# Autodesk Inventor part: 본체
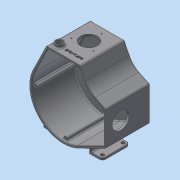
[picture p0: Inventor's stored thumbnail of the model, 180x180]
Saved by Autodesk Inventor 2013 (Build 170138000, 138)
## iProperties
Created: 2017-05
Part Number: 본체
Material: 알루미늄 6061
Document SubType Name: Modeling
Designer: mduedu
Density: 2.71 g/cm^3
Mass: 1300.76 g
Surface Area: 1825.93 cm^2
Volume: 479.984 cm^3
Author: mduedu
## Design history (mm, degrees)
sketch "스케치1"
  geometry: L1 (-71.801, 35.28)-(-40, 100); L2 (-40, 100)-(40, 100); L3 (40, 100)-(59.768, 59.768); L4 (59.768, 59.768)-(100, 40); L5 (100, 40)-(100, -40); L6 (100, -40)-(35.28, -71.801); A1 r 80 centre (0, 0) between (-71.801, 35.28) and (35.28, -71.801); 3 further points
  constraints: 12 end point, 4 tangent, 2 midpoint, 2 point on circle, 1 centre point, 1 coincident, 1 horizontal, 1 horizontal alignment, 1 perpendicular, 1 vertical alignment
  dimensions: "d0" = 160 diameter of A1; "d2" = 100 distance from line of L2 point (0, 0); "d3" = 100 distance from line of L5 point (0, 0); "d4" = 80 distance of L1.end L2.end; "d5" = 80 distance of L4.end L5.end
extrude "돌출1" new body sketch "스케치1" distance "d6" = 5; taper "d7" = 0 deg
fillet "모깎기1" dims "d8" = 50
sketch "스케치2"
  geometry: C1 r 22 at (0, 0); 1 further point
  constraints: 1 centre point, 1 coincident
  dimensions: "d9" = 44 diameter of C1
extrude "돌출2" join sketch "스케치2" distance "d10" = 22.5; taper "d11" = 0 deg
sketch "스케치3"
  geometry: C1 r 18.5 at (0, 0); 1 further point
  constraints: 1 centre point, 1 coincident
  dimensions: "d12" = 37 diameter of C1
extrude "돌출3" cut sketch "스케치3" distance "d13" = 9; taper "d14" = 0 deg
fillet "모깎기2" dims "d15" = 3
sketch "스케치4"
  geometry: L1 (35.28, -71.801)-(100, -40) reference; L2 (100, -40)-(100, 40) reference; L3 (100, 40)-(75.073, 52.248) reference; L4 (52.248, 75.073)-(40, 100) reference; L5 (40, 100)-(-40, 100) reference; L6 (-40, 100)-(-71.801, 35.28) reference; L7 (-36.886, 95)-(36.886, 95); L8 (36.886, 95)-(47.76, 72.868); L9 (72.868, 47.76)-(95, 36.886); L10 (95, 36.886)-(95, -36.886); L11 (95, -36.886)-(33.075, -67.313); L12 (-67.313, 33.075)-(-36.886, 95); C1 r 25 at (0, 0) reference; A1 r 50 centre (97.123, 97.123) between (52.248, 75.073) and (75.073, 52.248) reference; A2 r 80 centre (0, 0) between (-71.801, 35.28) and (35.28, -71.801) reference; A3 r 55 centre (97.123, 97.123) between (47.76, 72.868) and (72.868, 47.76); A4 r 75 centre (0, 0) between (-67.313, 33.075) and (33.075, -67.313); 1 further point
  constraints: 12 end point, 4 point on circle, 2 centre point, 7 other
  dimensions: "d16" = 5 distance between parallel lines of L7 L5
extrude "돌출4" join sketch "스케치4" distance "d17" = 100; taper "d18" = 0 deg
sketch "스케치5"
  geometry: L1 (80, 0)-(0, 0) reference; C1 r 20 at (40, -45); 2 further points
  constraints: 1 centre point, 1 midpoint, 1 vertical alignment
  dimensions: "d19" = 40 diameter of C1; "d21" = 45 distance from line of C1.centre L1
extrude "돌출5" cut sketch "스케치5" stored distance "d22" = 100; taper "d23" = 0 deg
sketch "스케치6"
  geometry: L1 (0, 0)-(0, -105) reference; L2 (80, -105)-(0, -105) reference; C1 r 9 at (14, -89); 1 further point
  constraints: 1 centre point
  dimensions: "d24" = 18 diameter of C1; "d26" = 14 distance from line of C1.centre L1; "d27" = 16 distance from line of C1.centre L2
extrude "돌출6" join sketch "스케치6" distance "d28" = 7; taper "d29" = 0 deg
hole "구멍1" diameter "d32" = 14; stored, may be unused: countersink angle "d36" = 90 deg, drill point angle "d38" = 118 deg; dims "d33" = 6, "d34" = 4, "d35" = 2, "d37" = 8, "d39" = 10, "d40" = 10
sketch "스케치7"
  geometry: L1 (-105, 0)-(-105, 80) reference; L2 (0, 0)-(0, 80) reference; C1 r 20 at (-70, 40); 2 further points
  constraints: 1 centre point, 1 horizontal alignment, 1 midpoint
  dimensions: "d41" = 40 diameter of C1; "d42" = 35 distance from line of C1.centre L1
extrude "돌출7" cut sketch "스케치7" stored distance "d43" = 7; taper "d44" = 0 deg
node "작업 평면1"
sketch "스케치8"
  geometry: L1 (47.76, 72.868)-(36.886, 95) reference; L2 (36.886, 95)-(-36.886, 95) reference; L3 (-36.886, 95)-(-67.313, 33.075) reference; L4 (33.075, -67.313)-(95, -36.886) reference; L5 (95, -36.886)-(95, 36.886) reference; L6 (95, 36.886)-(72.868, 47.76) reference; L7 (95, 36.886)-(95, -36.886) reference; L8 (-36.886, 95)-(36.886, 95) reference; L9 (36.886, 95)-(47.76, 72.868) reference; L10 (-71, 4)-(-74.893, 4); L11 (-71, -4)-(-74.893, -4); L12 (-4, -71)-(-4, -74.893); L13 (4, -71)-(4, -74.893); L14 (30.394, 91)-(30.394, 95); L15 (34.394, 87)-(40.817, 87); L16 (30.394, 95)-(36.886, 95); L17 (36.886, 95)-(37.984, 92.764); L18 (91, 30.394)-(95, 30.394); L19 (87, 34.394)-(87, 40.817); L20 (87, 40.817)-(95, 36.886); L21 (95, 36.886)-(95, 30.394); C1 r 25 at (0, 0) reference; A1 r 75 centre (0, 0) between (-67.313, 33.075) and (33.075, -67.313) reference; A2 r 55 centre (97.123, 97.123) between (47.76, 72.868) and (72.868, 47.76) reference; A3 r 4 centre (-71, 0) between (-71, 4) and (-71, -4); A4 r 4 centre (0, -71) between (-4, -71) and (4, -71); A5 r 4 centre (34.394, 91) between (30.394, 91) and (34.394, 87); A6 r 75 centre (0, 0) between (-67.313, 33.075) and (33.075, -67.313) reference; A7 r 4 centre (91, 34.394) between (91, 30.394) and (87, 34.394); 1 further point
  constraints: 24 end point, 17 point on circle, 14 tangent, 5 point on line, 4 centre point, 3 equal radius, 3 perpendicular, 3 vertical, 2 collinear, 2 horizontal, 1 horizontal alignment, 1 parallel, 1 vertical alignment
  dimensions: "d46" = 8 diameter of A3
extrude "돌출8" join sketch "스케치8" stored distance "d49" = 7; taper "d50" = 0 deg
node "작업 평면2"
sketch "스케치9"
  geometry: L1 (71.801, 0)-(71.801, 105) reference; L2 (71.801, 0)-(-35.28, 0) reference; L3 (-35.28, 0)-(-35.28, 105) reference; L4 (71.801, 105)-(-35.28, 105) reference; L5 (40, 0)-(40, 105) reference; L6 (71.801, 52.5)-(-35.28, 52.5); L7 (71.801, 20)-(40, 20); L8 (40, 20)-(40, 85); L9 (40, 85)-(71.801, 85); L10 (71.801, 85)-(71.801, 20); 1 further point
  constraints: 10 end point, 2 midpoint, 2 parallel, 2 point on line, 1 horizontal, 1 perpendicular, 1 other
  dimensions: "d52" = 20 distance between parallel lines of L7 L2
extrude "돌출9" join sketch "스케치9" distance "d53" = 5; taper "d54" = 0 deg
fillet "모깎기3" dims "d55" = 8
sketch "스케치10"
  geometry: C1 r 4 at (-63.801, -28); C2 r 4 at (-63.801, -77); A1 r 8 centre (-63.801, -28) between (-63.801, -20) and (-71.801, -28) reference; A2 r 8 centre (-63.801, -77) between (-71.801, -77) and (-63.801, -85) reference; 1 further point
  constraints: 2 centre point, 2 coincident, 1 equal radius
  dimensions: "d56" = 8 diameter of C1
extrude "돌출10" cut sketch "스케치10" stored distance "d57" = 50.5; taper "d58" = 0 deg
sketch "스케치11"
  geometry: L1 (-63.801, -20)-(-40, -20) reference; L2 (-40, -20)-(-40, -85) reference; L3 (-40, -85)-(-63.801, -85) reference; L4 (-71.801, -77)-(-71.801, -28) reference; L5 (71.801, -77)-(71.801, -28) reference; L6 (40, -85)-(63.801, -85) reference; L7 (40, -20)-(40, -85) reference; L8 (63.801, -20)-(40, -20) reference; L9 (-40, -85)-(-45, -85); L10 (-45, -85)-(-45, -20); L11 (-45, -20)-(-40, -20); L12 (-40, -20)-(-40, -85); L13 (40, -85)-(45, -85); L14 (45, -85)-(45, -20); L15 (45, -20)-(40, -20); L16 (40, -20)-(40, -85); C1 r 4 at (-63.801, -28) reference; C2 r 4 at (-63.801, -77) reference; C3 r 4 at (63.801, -28) reference; C4 r 4 at (63.801, -77) reference; A1 r 8 centre (-63.801, -28) between (-63.801, -20) and (-71.801, -28) reference; A2 r 8 centre (-63.801, -77) between (-71.801, -77) and (-63.801, -85) reference; A3 r 8 centre (63.801, -28) between (71.801, -28) and (63.801, -20) reference; A4 r 8 centre (63.801, -77) between (63.801, -85) and (71.801, -77) reference; 1 further point
  constraints: 16 end point, 4 parallel, 2 horizontal, 2 perpendicular, 2 point on line
  dimensions: "d59" = 5 distance of L10.end L11.end; "d61" = 5 distance of L14.end L15.end
extrude "돌출11" join sketch "스케치11" stored distance "d62" = 5; taper "d63" = 0 deg
fillet "모깎기4" dims "d64" = 3
fillet "모깎기5" dims "d65" = 1
fillet "모깎기6" dims "d66" = 1
fillet "모깎기8" dims "d68" = 1
fillet "모깎기9" dims "d70" = 3, "d101" = 1
fillet "모깎기10" dims "d71" = 3
fillet "모깎기11" dims "d72" = 3
fillet "모깎기12" dims "d73" = 3
fillet "모깎기13" dims "d76" = 3
chamfer "모따기1" distance "d77" = 0.5; stored, may be unused: second distance "d78" = 2, angle "d79" = 45 deg
sketch "스케치13"
  geometry: L1 (76.263, 0)-(0, 0) reference; 2 further points
  constraints: 1 other
  dimensions: "d83" = 15 distance from line of point (48.131, 15) L1; "d84" = 10 horizontal distance of point (48.131, 15) point (38.131, 105)
feature "엠보싱1" sketch "스케치13" dims "d0" = 160, "d2" = 100, "d3" = 100, "d4" = 80, "d5" = 80, "d85" = 0.5, "d86" = 0
chamfer "모따기2" distance "d87" = 1; stored, may be unused: second distance "d88" = 2, angle "d89" = 45 deg
chamfer "모따기3" distance "d90" = 1; stored, may be unused: second distance "d91" = 2, angle "d92" = 45 deg
sketch "스케치14"
  geometry: 3 further points
  constraints: 3 other
hole "구멍2" sketch "스케치14" at (-55.375, -40), (-3.414, -40), (-29.394, -85) diameter "d93" = 2.459; stored, may be unused: countersink angle "d97" = 90 deg, drill point angle "d99" = 0 deg; dims "d94" = 6, "d95" = 4, "d96" = 2, "d98" = 8
sketch "스케치15"
  geometry: 3 further points
  constraints: 3 other
hole "구멍4" sketch "스케치15" at (-55.981, -14.394), (-4.019, -14.394), (-30, -59.394) diameter "d102" = 2.459; stored, may be unused: countersink angle "d106" = 90 deg, drill point angle "d108" = 0 deg; dims "d103" = 6, "d104" = 4, "d105" = 2, "d107" = 8
sketch "스케치16"
  geometry: 4 further points
  constraints: 4 other
hole "구멍6" sketch "스케치16" at (0, -71), (91, 34.394), (34.394, 91), (-71, 0) diameter "d109" = 2.459; stored, may be unused: countersink angle "d113" = 90 deg, drill point angle "d115" = 120 deg; dims "d110" = 8.5, "d111" = 4, "d112" = 2, "d114" = 10
node "솔리드1"
mirror "대칭1"
node "투영된 루프1"
node "투영된 루프2"
node "투영된 루프3"
node "투영된 루프4"
node "투영된 루프5"
other parameters: "d45" = 95
